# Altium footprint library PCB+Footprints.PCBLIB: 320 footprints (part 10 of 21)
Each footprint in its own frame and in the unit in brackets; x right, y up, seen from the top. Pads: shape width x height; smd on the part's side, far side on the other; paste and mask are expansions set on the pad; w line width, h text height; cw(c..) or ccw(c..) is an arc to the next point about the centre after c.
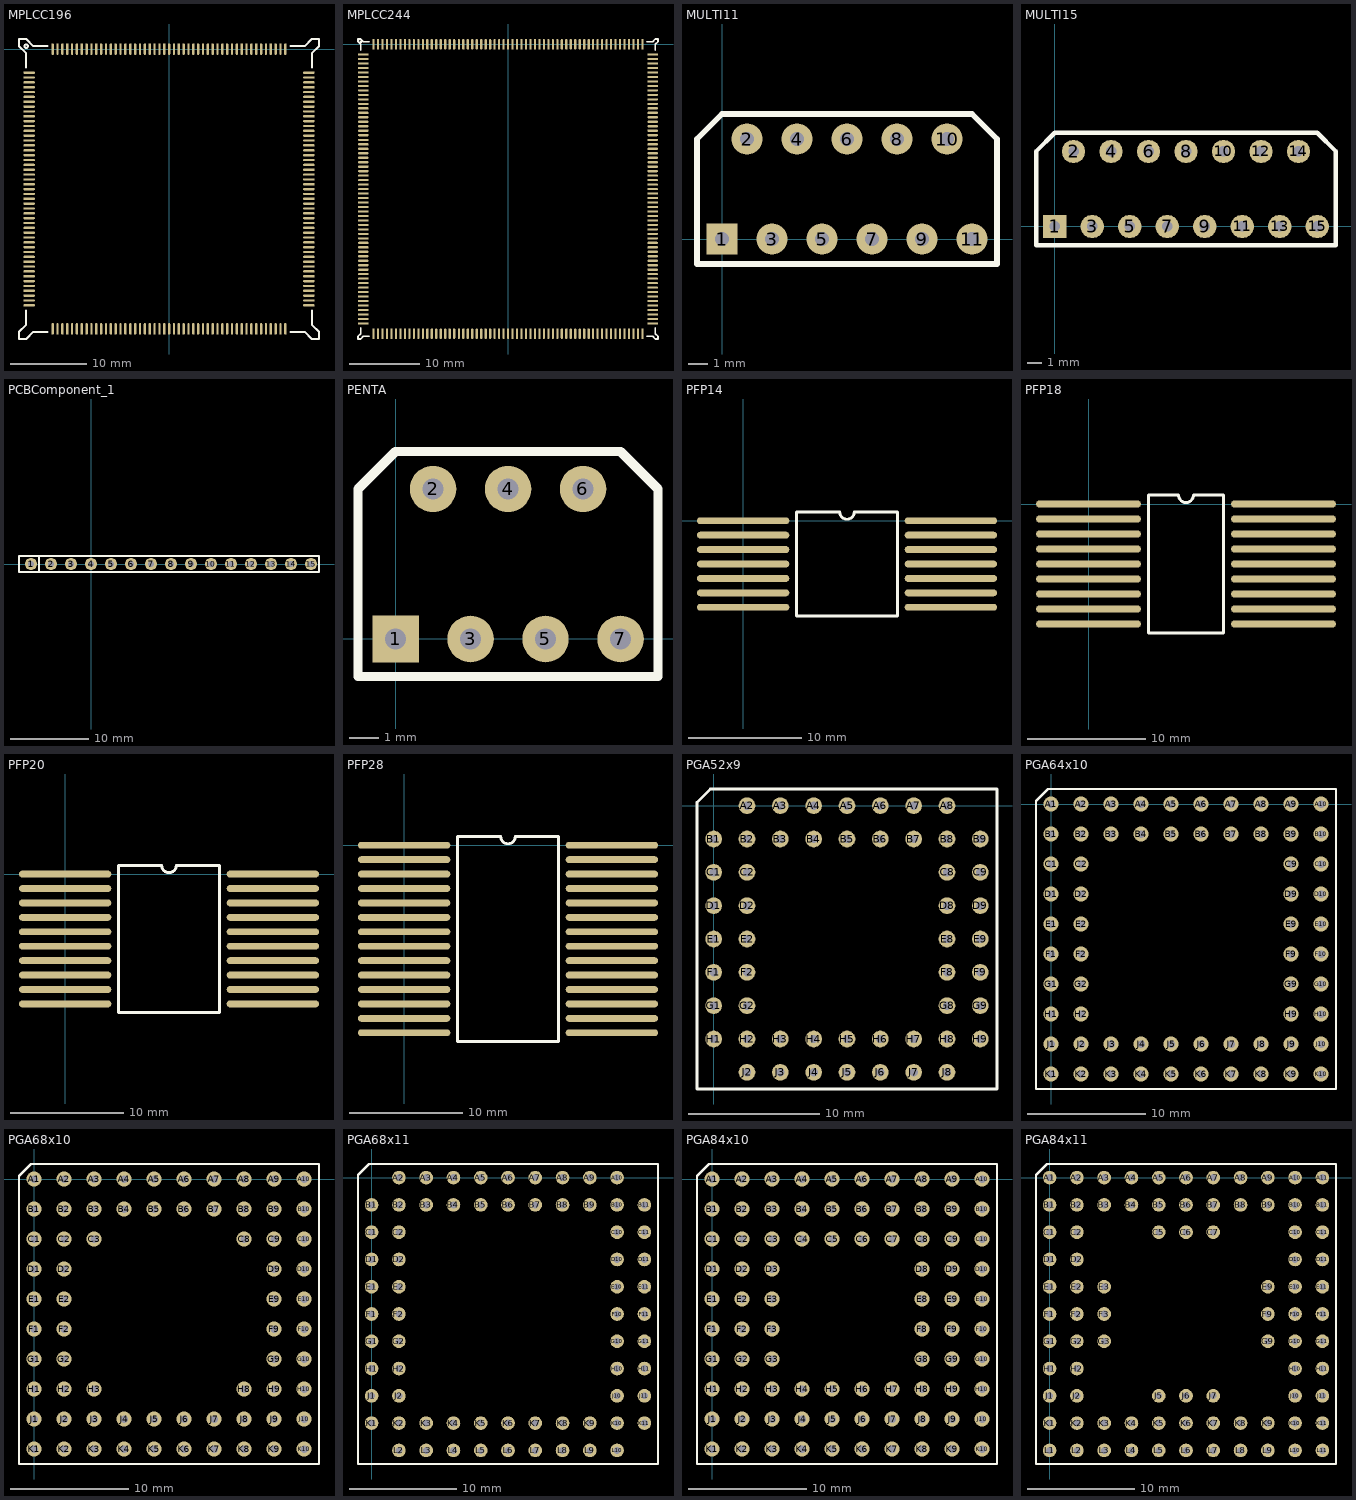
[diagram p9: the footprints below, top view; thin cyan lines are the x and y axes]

## MPLCC196 [mil]
pads (196):
  oval 12x60 smd: 1(0,0) 2(-25,0) 3(-50,0) 4(-75,0) 5(-100,0) 6(-125,0) 7(-150,0) 8(-175,0) 9(-200,0) 10(-226,0) 11(-251,0) 12(-276,0) 13(-301,0) 14(-326,0) 15(-351,0) 16(-376,0) 17(-401,0) 18(-426,0) 19(-451,0) 20(-476,0) 21(-501,0) 22(-526,0) 23(-551,0) 24(-576,0) 25(-601,0) 75(-601,-1445) 76(-576,-1445) 77(-551,-1445) 78(-526,-1445) 79(-501,-1445) 80(-476,-1445) 81(-451,-1445) 82(-426,-1445) 83(-401,-1445) 84(-376,-1445) 85(-351,-1445) 86(-326,-1445) 87(-301,-1445) 88(-276,-1445) 89(-251,-1445) 90(-226,-1445) 91(-200,-1445) 92(-175,-1445) 93(-150,-1445) 94(-125,-1445) 95(-100,-1445) 96(-75,-1445) 97(-50,-1445) 98(-25,-1445) 99(0,-1445) 100(25,-1445) 101(50,-1445) 102(75,-1445) 103(100,-1445) 104(125,-1445) 105(150,-1445) 106(175,-1445) 107(200,-1445) 108(225,-1445) 109(250,-1445) 110(275,-1445) 111(300,-1445) 112(325,-1445) 113(350,-1445) 114(375,-1445) 115(400,-1445) 116(425,-1445) 117(450,-1445) 118(475,-1445) 119(500,-1445) 120(525,-1445) 121(550,-1445) 122(575,-1445) 123(600,-1445) 173(600,0) 174(575,0) 175(550,0) 176(525,0) 177(500,0) 178(475,0) 179(450,0) 180(425,0) 181(400,0) 182(375,0) 183(350,0) 184(325,0) 185(300,0) 186(275,0) 187(250,0) 188(225,0) 189(200,0) 190(175,0) 191(150,0) 192(125,0) 193(100,0) 194(75,0) 195(50,0) 196(25,0)
  oval 60x12 smd: 26(-723,-122) 27(-723,-147) 28(-723,-172) 29(-723,-197) 30(-723,-222) 31(-723,-247) 32(-723,-272) 33(-723,-297) 34(-723,-322) 35(-723,-347) 36(-723,-372) 37(-723,-397) 38(-723,-422) 39(-723,-447) 40(-723,-472) 41(-723,-497) 42(-723,-523) 43(-723,-548) 44(-723,-573) 45(-723,-598) 46(-723,-623) 47(-723,-648) 48(-723,-673) 49(-723,-698) 50(-723,-723) 51(-723,-748) 52(-723,-773) 53(-723,-798) 54(-723,-823) 55(-723,-848) 56(-723,-873) 57(-723,-898) 58(-723,-923) 59(-723,-948) 60(-723,-973) 61(-723,-998) 62(-723,-1023) 63(-723,-1048) 64(-723,-1073) 65(-723,-1098) 66(-723,-1123) 67(-723,-1148) 68(-723,-1173) 69(-723,-1198) 70(-723,-1223) 71(-723,-1248) 72(-723,-1273) 73(-723,-1298) 74(-723,-1323) 124(722,-1323) 125(722,-1298) 126(722,-1273) 127(722,-1248) 128(722,-1223) 129(722,-1198) 130(722,-1173) 131(722,-1148) 132(722,-1123) 133(722,-1098) 134(722,-1073) 135(722,-1048) 136(722,-1023) 137(722,-998) 138(722,-973) 139(722,-948) 140(722,-923) 141(722,-898) 142(722,-873) 143(722,-848) 144(722,-823) 145(722,-798) 146(722,-773) 147(722,-748) 148(722,-723) 149(722,-698) 150(722,-673) 151(722,-648) 152(722,-623) 153(722,-598) 154(722,-573) 155(722,-548) 156(722,-523) 157(722,-497) 158(722,-472) 159(722,-447) 160(722,-422) 161(722,-397) 162(722,-372) 163(722,-347) 164(722,-322) 165(722,-297) 166(722,-272) 167(722,-247) 168(722,-222) 169(722,-197) 170(722,-172) 171(722,-147) 172(722,-122)
TopOverlay:
  circle w10: c-738,15 r9
  lines w10: -738,-1349 -738,-1423 -775,-1460 -775,-1497 -738,-1497 -701,-1460 -627,-1460 ; -738,-96 -738,-22 -775,15 -775,52 -738,52 -701,15 -627,15 ; 626,-1460 700,-1460 737,-1497 774,-1497 774,-1460 737,-1423 737,-1349 ; 626,15 700,15 737,52 774,52 774,15 737,-22 737,-96

## MPLCC244 [mil]
pads (244):
  oval 12x60 smd: 1(0,0) 2(-25,0) 3(-50,0) 4(-75,0) 5(-100,0) 6(-125,0) 7(-150,0) 8(-175,0) 9(-200,0) 10(-225,0) 11(-250,0) 12(-275,0) 13(-301,0) 14(-326,0) 15(-351,0) 16(-376,0) 17(-401,0) 18(-426,0) 19(-451,0) 20(-476,0) 21(-501,0) 22(-526,0) 23(-551,0) 24(-576,0) 25(-601,0) 26(-626,0) 27(-651,0) 28(-676,0) 29(-701,0) 30(-726,0) 31(-751,0) 93(-751,-1615) 94(-726,-1615) 95(-701,-1615) 96(-676,-1615) 97(-651,-1615) 98(-626,-1615) 99(-601,-1615) 100(-576,-1615) 101(-551,-1615) 102(-526,-1615) 103(-501,-1615) 104(-476,-1615) 105(-451,-1615) 106(-426,-1615) 107(-401,-1615) 108(-376,-1615) 109(-351,-1615) 110(-326,-1615) 111(-301,-1615) 112(-275,-1615) 113(-250,-1615) 114(-225,-1615) 115(-200,-1615) 116(-175,-1615) 117(-150,-1615) 118(-125,-1615) 119(-100,-1615) 120(-75,-1615) 121(-50,-1615) 122(-25,-1615) 123(0,-1615) 124(25,-1615) 125(50,-1615) 126(75,-1615) 127(100,-1615) 128(125,-1615) 129(150,-1615) 130(175,-1615) 131(200,-1615) 132(225,-1615) 133(250,-1615) 134(275,-1615) 135(300,-1615) 136(325,-1615) 137(350,-1615) 138(375,-1615) 139(400,-1615) 140(425,-1615) 141(450,-1615) 142(475,-1615) 143(500,-1615) 144(525,-1615) 145(550,-1615) 146(575,-1615) 147(600,-1615) 148(625,-1615) 149(650,-1615) 150(675,-1615) 151(700,-1615) 152(725,-1615) 153(750,-1615) 215(750,0) 216(725,0) 217(700,0) 218(675,0) 219(650,0) 220(625,0) 221(600,0) 222(575,0) 223(550,0) 224(525,0) 225(500,0) 226(475,0) 227(450,0) 228(425,0) 229(400,0) 230(375,0) 231(350,0) 232(325,0) 233(300,0) 234(275,0) 235(250,0) 236(225,0) 237(200,0) 238(175,0) 239(150,0) 240(125,0) 241(100,0) 242(75,0) 243(50,0) 244(25,0)
  oval 60x12 smd: 32(-808,-57) 33(-808,-82) 34(-808,-107) 35(-808,-132) 36(-808,-157) 37(-808,-182) 38(-808,-207) 39(-808,-232) 40(-808,-257) 41(-808,-282) 42(-808,-307) 43(-808,-332) 44(-808,-357) 45(-808,-382) 46(-808,-407) 47(-808,-432) 48(-808,-457) 49(-808,-482) 50(-808,-507) 51(-808,-533) 52(-808,-558) 53(-808,-583) 54(-808,-608) 55(-808,-633) 56(-808,-658) 57(-808,-683) 58(-808,-708) 59(-808,-733) 60(-808,-758) 61(-808,-783) 62(-808,-808) 63(-808,-833) 64(-808,-858) 65(-808,-883) 66(-808,-908) 67(-808,-933) 68(-808,-958) 69(-808,-983) 70(-808,-1008) 71(-808,-1033) 72(-808,-1058) 73(-808,-1083) 74(-808,-1108) 75(-808,-1133) 76(-808,-1158) 77(-808,-1183) 78(-808,-1208) 79(-808,-1233) 80(-808,-1258) 81(-808,-1283) 82(-808,-1308) 83(-808,-1333) 84(-808,-1358) 85(-808,-1383) 86(-808,-1408) 87(-808,-1433) 88(-808,-1458) 89(-808,-1483) 90(-808,-1508) 91(-808,-1533) 92(-808,-1558) 154(807,-1558) 155(807,-1533) 156(807,-1508) 157(807,-1483) 158(807,-1458) 159(807,-1433) 160(807,-1408) 161(807,-1383) 162(807,-1358) 163(807,-1333) 164(807,-1308) 165(807,-1283) 166(807,-1258) 167(807,-1233) 168(807,-1208) 169(807,-1183) 170(807,-1158) 171(807,-1133) 172(807,-1108) 173(807,-1083) 174(807,-1058) 175(807,-1033) 176(807,-1008) 177(807,-983) 178(807,-958) 179(807,-933) 180(807,-908) 181(807,-883) 182(807,-858) 183(807,-833) 184(807,-808) 185(807,-783) 186(807,-758) 187(807,-733) 188(807,-708) 189(807,-683) 190(807,-658) 191(807,-633) 192(807,-608) 193(807,-583) 194(807,-558) 195(807,-533) 196(807,-507) 197(807,-482) 198(807,-457) 199(807,-432) 200(807,-407) 201(807,-382) 202(807,-357) 203(807,-332) 204(807,-307) 205(807,-282) 206(807,-257) 207(807,-232) 208(807,-207) 209(807,-182) 210(807,-157) 211(807,-132) 212(807,-107) 213(807,-82) 214(807,-57)
TopOverlay:
  circle w10: c-823,15 r3
  lines w10: -823,-1584 -823,-1615 -838,-1630 -838,-1645 -823,-1645 -808,-1630 -777,-1630 ; -823,-31 -823,0 -838,15 -838,30 -823,30 -808,15 -777,15 ; 776,-1630 807,-1630 822,-1645 837,-1645 837,-1630 822,-1615 822,-1584 ; 776,15 807,15 822,30 837,30 837,15 822,0 822,-31

## MULTI11 [mil]
pads (11):
  rect 62x62 hole 28: 1(0,0)
  round 62 hole 28: 2(50,200) 3(100,0) 4(150,200) 5(200,0) 6(250,200) 7(300,0) 8(350,200) 9(400,0) 10(450,200) 11(500,0)
TopOverlay:
  lines w12: -50,-50 550,-50 550,200 500,250 0,250 -50,200 -50,-50

## MULTI15 [mil]
pads (15):
  rect 62x62 hole 28: 1(0,0)
  round 62 hole 28: 2(50,200) 3(100,0) 4(150,200) 5(200,0) 6(250,200) 7(300,0) 8(350,200) 9(400,0) 10(450,200) 11(500,0) 12(550,200) 13(600,0) 14(650,200) 15(700,0)
TopOverlay:
  lines w12: -50,-50 750,-50 750,200 700,250 0,250 -50,200 -50,-50

## PCBComponent_1 [mil]
pads (15):
  round 60 hole 30: 1(-300,0) 2(-200,0) 3(-100,0) 4(0,0) 5(100,0) 6(200,0) 7(300,0) 8(400,0) 9(500,0) 10(600,0) 11(700,0) 12(800,0) 13(900,0) 14(1000,0) 15(1100,0)
TopOverlay:
  lines w10: -260,-40 -260,40 ; -360,-40 -360,40 1140,40 1140,-40 -360,-40

## PENTA [mil]
pads (7):
  rect 62x62 hole 28: 1(0,0)
  round 62 hole 28: 2(50,200) 3(100,0) 4(150,200) 5(200,0) 6(250,200) 7(300,0)
TopOverlay:
  lines w12: -50,-50 350,-50 350,200 300,250 0,250 -50,200 -50,-50

## PFP14 [mil]
pads (14):
  oval 320x24 smd: 1(0,0) 2(0,-50) 3(0,-100) 4(0,-150) 5(0,-200) 6(0,-250) 7(0,-300) 8(720,-300) 9(720,-250) 10(720,-200) 11(720,-150) 12(720,-100) 13(720,-50) 14(720,0)
TopOverlay:
  lines w10: 185,-330 535,-330 535,30 385,30 cw(c360,30) 335,30 185,30 185,-330

## PFP18 [mil]
pads (18):
  oval 350x24 smd: 1(0,0) 2(0,-50) 3(0,-100) 4(0,-150) 5(0,-200) 6(0,-250) 7(0,-300) 8(0,-350) 9(0,-400) 10(650,-400) 11(650,-350) 12(650,-300) 13(650,-250) 14(650,-200) 15(650,-150) 16(650,-100) 17(650,-50) 18(650,0)
TopOverlay:
  lines w10: 200,-430 450,-430 450,30 350,30 cw(c325,30) 300,30 200,30 200,-430

## PFP20 [mil]
pads (20):
  oval 320x24 smd: 1(0,0) 2(0,-50) 3(0,-100) 4(0,-150) 5(0,-200) 6(0,-250) 7(0,-300) 8(0,-350) 9(0,-400) 10(0,-450) 11(720,-450) 12(720,-400) 13(720,-350) 14(720,-300) 15(720,-250) 16(720,-200) 17(720,-150) 18(720,-100) 19(720,-50) 20(720,0)
TopOverlay:
  lines w10: 185,-480 535,-480 535,30 385,30 cw(c360,30) 335,30 185,30 185,-480

## PFP28 [mil]
pads (28):
  oval 320x24 smd: 1(0,0) 2(0,-50) 3(0,-100) 4(0,-150) 5(0,-200) 6(0,-250) 7(0,-300) 8(0,-350) 9(0,-400) 10(0,-450) 11(0,-500) 12(0,-550) 13(0,-600) 14(0,-650) 15(720,-650) 16(720,-600) 17(720,-550) 18(720,-500) 19(720,-450) 20(720,-400) 21(720,-350) 22(720,-300) 23(720,-250) 24(720,-200) 25(720,-150) 26(720,-100) 27(720,-50) 28(720,0)
TopOverlay:
  lines w10: 185,-680 535,-680 535,30 385,30 cw(c360,30) 335,30 185,30 185,-680

## PGA52x9 [mil]
pads (52):
  round 50 hole 25: A2(100,0) A3(200,0) A4(300,0) A5(400,0) A6(500,0) A7(600,0) A8(700,0) B1(0,-100) B2(100,-100) B3(200,-100) B4(300,-100) B5(400,-100) B6(500,-100) B7(600,-100) B8(700,-100) B9(800,-100) C1(0,-200) C2(100,-200) C8(700,-200) C9(800,-200) D1(0,-300) D2(100,-300) D8(700,-300) D9(800,-300) E1(0,-400) E2(100,-400) E8(700,-400) E9(800,-400) F1(0,-500) F2(100,-500) F8(700,-500) F9(800,-500) G1(0,-600) G2(100,-600) G8(700,-600) G9(800,-600) H1(0,-700) H2(100,-700) H3(200,-700) H4(300,-700) H5(400,-700) H6(500,-700) H7(600,-700) H8(700,-700) H9(800,-700) J2(100,-800) J3(200,-800) J4(300,-800) J5(400,-800) J6(500,-800) J7(600,-800) J8(700,-800)
TopOverlay:
  lines w8: -50,-850 850,-850 850,50 -10,50 -50,10 -50,-850

## PGA64x10 [mil]
pads (64):
  round 50 hole 25: A1(0,0) A2(100,0) A3(200,0) A4(300,0) A5(400,0) A6(500,0) A7(600,0) A8(700,0) A9(800,0) A10(900,0) B1(0,-100) B2(100,-100) B3(200,-100) B4(300,-100) B5(400,-100) B6(500,-100) B7(600,-100) B8(700,-100) B9(800,-100) B10(900,-100) C1(0,-200) C2(100,-200) C9(800,-200) C10(900,-200) D1(0,-300) D2(100,-300) D9(800,-300) D10(900,-300) E1(0,-400) E2(100,-400) E9(800,-400) E10(900,-400) F1(0,-500) F2(100,-500) F9(800,-500) F10(900,-500) G1(0,-600) G2(100,-600) G9(800,-600) G10(900,-600) H1(0,-700) H2(100,-700) H9(800,-700) H10(900,-700) J1(0,-800) J2(100,-800) J3(200,-800) J4(300,-800) J5(400,-800) J6(500,-800) J7(600,-800) J8(700,-800) J9(800,-800) J10(900,-800) K1(0,-900) K2(100,-900) K3(200,-900) K4(300,-900) K5(400,-900) K6(500,-900) K7(600,-900) K8(700,-900) K9(800,-900) K10(900,-900)
TopOverlay:
  lines w8: -50,-950 950,-950 950,50 -10,50 -50,10 -50,-950

## PGA68x10 [mil]
pads (68):
  round 50 hole 25: A1(0,0) A2(100,0) A3(200,0) A4(300,0) A5(400,0) A6(500,0) A7(600,0) A8(700,0) A9(800,0) A10(900,0) B1(0,-100) B2(100,-100) B3(200,-100) B4(300,-100) B5(400,-100) B6(500,-100) B7(600,-100) B8(700,-100) B9(800,-100) B10(900,-100) C1(0,-200) C2(100,-200) C3(200,-200) C8(700,-200) C9(800,-200) C10(900,-200) D1(0,-300) D2(100,-300) D9(800,-300) D10(900,-300) E1(0,-400) E2(100,-400) E9(800,-400) E10(900,-400) F1(0,-500) F2(100,-500) F9(800,-500) F10(900,-500) G1(0,-600) G2(100,-600) G9(800,-600) G10(900,-600) H1(0,-700) H2(100,-700) H3(200,-700) H8(700,-700) H9(800,-700) H10(900,-700) J1(0,-800) J2(100,-800) J3(200,-800) J4(300,-800) J5(400,-800) J6(500,-800) J7(600,-800) J8(700,-800) J9(800,-800) J10(900,-800) K1(0,-900) K2(100,-900) K3(200,-900) K4(300,-900) K5(400,-900) K6(500,-900) K7(600,-900) K8(700,-900) K9(800,-900) K10(900,-900)
TopOverlay:
  lines w8: -50,-950 -50,10 -10,50 950,50 950,-950 -50,-950

## PGA68x11 [mil]
pads (68):
  round 50 hole 25: A2(100,0) A3(200,0) A4(300,0) A5(400,0) A6(500,0) A7(600,0) A8(700,0) A9(800,0) A10(900,0) B1(0,-100) B2(100,-100) B3(200,-100) B4(300,-100) B5(400,-100) B6(500,-100) B7(600,-100) B8(700,-100) B9(800,-100) B10(900,-100) B11(1000,-100) C1(0,-200) C2(100,-200) C10(900,-200) C11(1000,-200) D1(0,-300) D2(100,-300) D10(900,-300) D11(1000,-300) E1(0,-400) E2(100,-400) E10(900,-400) E11(1000,-400) F1(0,-500) F2(100,-500) F10(900,-500) F11(1000,-500) G1(0,-600) G2(100,-600) G10(900,-600) G11(1000,-600) H1(0,-700) H2(100,-700) H10(900,-700) H11(1000,-700) J1(0,-800) J2(100,-800) J10(900,-800) J11(1000,-800) K1(0,-900) K2(100,-900) K3(200,-900) K4(300,-900) K5(400,-900) K6(500,-900) K7(600,-900) K8(700,-900) K9(800,-900) K10(900,-900) K11(1000,-900) L2(100,-1000) L3(200,-1000) L4(300,-1000) L5(400,-1000) L6(500,-1000) L7(600,-1000) L8(700,-1000) L9(800,-1000) L10(900,-1000)
TopOverlay:
  lines w8: -50,-1050 1050,-1050 1050,50 -10,50 -50,10 -50,-1050

## PGA84x10 [mil]
pads (84):
  round 50 hole 25: A1(0,0) A2(100,0) A3(200,0) A4(300,0) A5(400,0) A6(500,0) A7(600,0) A8(700,0) A9(800,0) A10(900,0) B1(0,-100) B2(100,-100) B3(200,-100) B4(300,-100) B5(400,-100) B6(500,-100) B7(600,-100) B8(700,-100) B9(800,-100) B10(900,-100) C1(0,-200) C2(100,-200) C3(200,-200) C4(300,-200) C5(400,-200) C6(500,-200) C7(600,-200) C8(700,-200) C9(800,-200) C10(900,-200) D1(0,-300) D2(100,-300) D3(200,-300) D8(700,-300) D9(800,-300) D10(900,-300) E1(0,-400) E2(100,-400) E3(200,-400) E8(700,-400) E9(800,-400) E10(900,-400) F1(0,-500) F2(100,-500) F3(200,-500) F8(700,-500) F9(800,-500) F10(900,-500) G1(0,-600) G2(100,-600) G3(200,-600) G8(700,-600) G9(800,-600) G10(900,-600) H1(0,-700) H2(100,-700) H3(200,-700) H4(300,-700) H5(400,-700) H6(500,-700) H7(600,-700) H8(700,-700) H9(800,-700) H10(900,-700) J1(0,-800) J2(100,-800) J3(200,-800) J4(300,-800) J5(400,-800) J6(500,-800) J7(600,-800) J8(700,-800) J9(800,-800) J10(900,-800) K1(0,-900) K2(100,-900) K3(200,-900) K4(300,-900) K5(400,-900) K6(500,-900) K7(600,-900) K8(700,-900) K9(800,-900) K10(900,-900)
TopOverlay:
  lines w8: -50,-950 950,-950 950,50 -10,50 -50,10 -50,-950

## PGA84x11 [mil]
pads (84):
  round 50 hole 25: A1(0,0) A2(100,0) A3(200,0) A4(300,0) A5(400,0) A6(500,0) A7(600,0) A8(700,0) A9(800,0) A10(900,0) A11(1000,0) B1(0,-100) B2(100,-100) B3(200,-100) B4(300,-100) B5(400,-100) B6(500,-100) B7(600,-100) B8(700,-100) B9(800,-100) B10(900,-100) B11(1000,-100) C1(0,-200) C2(100,-200) C5(400,-200) C6(500,-200) C7(600,-200) C10(900,-200) C11(1000,-200) D1(0,-300) D2(100,-300) D10(900,-300) D11(1000,-300) E1(0,-400) E2(100,-400) E3(200,-400) E9(800,-400) E10(900,-400) E11(1000,-400) F1(0,-500) F2(100,-500) F3(200,-500) F9(800,-500) F10(900,-500) F11(1000,-500) G1(0,-600) G2(100,-600) G3(200,-600) G9(800,-600) G10(900,-600) G11(1000,-600) H1(0,-700) H2(100,-700) H10(900,-700) H11(1000,-700) J1(0,-800) J2(100,-800) J5(400,-800) J6(500,-800) J7(600,-800) J10(900,-800) J11(1000,-800) K1(0,-900) K2(100,-900) K3(200,-900) K4(300,-900) K5(400,-900) K6(500,-900) K7(600,-900) K8(700,-900) K9(800,-900) K10(900,-900) K11(1000,-900) L1(0,-1000) L2(100,-1000) L3(200,-1000) L4(300,-1000) L5(400,-1000) L6(500,-1000) L7(600,-1000) L8(700,-1000) L9(800,-1000) L10(900,-1000) L11(1000,-1000)
TopOverlay:
  lines w8: -50,-1050 1050,-1050 1050,50 -10,50 -50,10 -50,-1050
